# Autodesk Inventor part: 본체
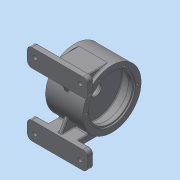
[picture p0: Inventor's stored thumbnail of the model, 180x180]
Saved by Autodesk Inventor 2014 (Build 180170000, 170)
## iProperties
Created: 2025-12
Part Number: 본체
Material: 일반
Document SubType Name: Modeling
Designer: dg
Density: 1 g/cm^3
Appearance: 기본값
Author: dg
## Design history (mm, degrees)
sketch "스케치1"
  geometry: L1 (-62, 0)-(62, 0); L2 (-62, 78)-(-57, 78); L3 (-57, 78)-(-57, 73); L4 (-57, 73)-(-40, 73); L5 (-40, 73)-(-40, 87); L6 (-40, 87)-(-8, 87); L7 (-8, 87)-(-8, 0); L8 (-8, 0)-(8, 0); L9 (8, 0)-(8, 87); L10 (8, 87)-(40, 87); L11 (40, 87)-(40, 73); L12 (40, 73)-(57, 73); L13 (57, 73)-(57, 78); L14 (57, 78)-(62, 78); L15 (62, 78)-(62, 97); L16 (62, 97)-(-62, 97); L17 (-62, 97)-(-62, 78); 2 further points
  constraints: 34 end point, 11 parallel, 4 perpendicular, 3 collinear, 3 horizontal alignment, 2 coincident, 2 point on line, 2 vertical alignment, 1 horizontal, 1 midpoint
  dimensions: "d0" = 124 distance of L1.start L1.end; "d1" = 146 diameter of L4 L1; "d2" = 156 diameter of L2 L1; "d3" = 174 diameter of L6 L1; "d4" = 194 diameter of L16 L1; "d5" = 5 distance of L2.start L2.end; "d7" = 32 distance of L5.end L6.end; "d48" = 22 distance between parallel lines of L5 L17
revolve "회전1" sketch "스케치1" stored, may be unused: angle "d8" = 90 deg
sketch "스케치2"
  geometry: L1 (0, -97)-(-100, -97); L2 (-100, -97)-(-100, -75); L3 (-100, -75)-(-61.514, -75); A1 r 97 centre (0, 0) between (0, -97) and (-61.514, -75) reference; 1 further point
  constraints: 6 end point, 2 point on circle, 1 horizontal, 1 parallel, 1 perpendicular, 1 tangent
  dimensions: "d9" = 22 distance of L1.end L2.end; "d10" = 100 distance from line of L2 L1.start
extrude "돌출1" join sketch "스케치2" stored distance "d11" = 100; taper "d12" = 0 deg
sketch "스케치3"
  geometry: L1 (-50, 22)-(150, 22); L2 (150, 22)-(150, -38); L3 (150, -38)-(-50, -38); L4 (-50, -38)-(-50, 22); 3 further points
  constraints: 8 end point, 2 parallel, 1 horizontal, 1 horizontal alignment, 1 midpoint, 1 perpendicular, 1 vertical alignment
  dimensions: "d13" = 200 distance of L2.end L3.end; "d14" = 60 distance of L3.end L1.start
extrude "돌출2" join sketch "스케치3" distance "d15" = 20; taper "d16" = 0 deg
sketch "스케치4"
  geometry: L1 (-100, -75)-(-61.514, -75) reference; L2 (-100, -75)-(-120, -75) reference; L3 (-112, -75)-(-89.83, -36.6); A1 r 97 centre (0, 0) between (-61.514, -75) and (-89.83, -36.6) reference; 1 further point
  constraints: 2 end point, 1 point on circle, 1 point on line
  dimensions: "d17" = 60 deg angle of L1 L3; "d18" = 8 distance of L2.end L3.start
extrude "돌출3" join sketch "스케치4" stored distance "d19" = 12; taper "d20" = 0 deg
fillet "모깎기1" dims "d21" = 15
sketch "스케치5"
  geometry: 3 further points
  constraints: 1 horizontal alignment
  dimensions: "d22" = 150 distance of point (125, 13) point (-25, 13); "d23" = 75 horizontal distance of point (50, -97) point (-25, 13); "d24" = 110 vertical distance of point (50, -97) point (125, 13)
hole "구멍1" sketch "스케치5" at (-25, 13), (125, 13) diameter "d25" = 13.5; stored, may be unused: countersink angle "d29" = 90 deg, drill point angle "d31" = 118 deg; dims "d26" = 6, "d27" = 33, "d28" = 2, "d30" = 8
fillet "모깎기2" dims "d32" = 3
fillet "모깎기3" dims "d33" = 3
fillet "모깎기4" dims "d34" = 3
fillet "모깎기5" dims "d35" = 3
fillet "모깎기6" dims "d36" = 3
fillet "모깎기7" dims "d37" = 3
fillet "모깎기8" dims "d38" = 3
fillet "모깎기9" dims "d39" = 3
fillet "모깎기10" dims "d40" = 3
fillet "모깎기11" dims "d41" = 3
fillet "모깎기12" dims "d42" = 3
fillet "모깎기13" dims "d43" = 3
sketch "스케치6"
  geometry: L1 (23.383, -39)-(37.148, -62.842); L2 (-23.383, -39)-(-37.148, -62.842); L3 (0, -25.5)-(0, -73); A1 r 73 centre (0, 0) between (37.148, -62.842) and (-37.148, -62.842) reference; A2 r 27 centre (0, -52.5) between (23.383, -39) and (-23.383, -39); 1 further point
  constraints: 6 end point, 6 point on circle, 2 tangent, 2 vertical alignment, 1 centre point, 1 midpoint, 1 vertical
  dimensions: "d44" = 54 diameter of A2; "d45" = 52.5 distance of A1.centre A2.centre; "d46" = 30 deg angle of L1 L3; "d47" = 30 deg angle of L3 L2
extrude "돌출4" join sketch "스케치6" distance "d49" = 17; taper "d50" = 0 deg
sketch "스케치7"
  geometry: A1 r 27 centre (0, -52.5) between (23.383, -39) and (-23.383, -39) reference; 1 further point
  constraints: 1 coincident
hole "구멍2" sketch "스케치7" at (0, -52.5) diameter "d51" = 42; stored, may be unused: countersink angle "d55" = 90 deg, drill point angle "d57" = 0 deg; dims "d52" = 6, "d53" = 33, "d54" = 2, "d56" = 3.05
hole "구멍3" diameter "d60" = 42; stored, may be unused: countersink angle "d64" = 90 deg, drill point angle "d66" = 0 deg; dims "d61" = 6, "d62" = 44.5, "d63" = 1.95, "d65" = 12, "d103" = 10, "d104" = 10
sketch "스케치9"
  geometry: C1 r 78 at (0, 0) reference; 1 further point
  constraints: 1 vertical alignment
  dimensions: "d67" = 85 distance of C1.centre point (0, 85)
hole "구멍4" sketch "스케치9" at (0, 85) diameter "d68" = 6.647; stored, may be unused: countersink angle "d72" = 90 deg, drill point angle "d74" = 118 deg; dims "d69" = 16, "d70" = 44.5, "d71" = 1.95, "d73" = 18
chamfer "모따기1" distance "d78" = 1; stored, may be unused: second distance "d79" = 2, angle "d80" = 45 deg
chamfer "모따기2" distance "d81" = 1; stored, may be unused: second distance "d82" = 2, angle "d83" = 45 deg
sketch "스케치10"
  geometry: C1 r 87 at (0, 0) reference; 2 further points
  constraints: 1 coincident, 1 vertical alignment
  dimensions: "d84" = 52.5 distance of point (0, -52.5) point (0, 0)
hole "구멍5" sketch "스케치10" at (0, 0), (0, -52.5) diameter "d85" = 38; stored, may be unused: countersink angle "d89" = 90 deg, drill point angle "d91" = 118 deg; dims "d86" = 16, "d87" = 42, "d88" = 12, "d90" = 18
chamfer "모따기3" distance "d92" = 1; stored, may be unused: second distance "d93" = 2, angle "d94" = 45 deg
fillet "모깎기14" dims "d95" = 0.6
fillet "모깎기15" dims "d96" = 3
fillet "모깎기16" dims "d97" = 3
fillet "모깎기17" dims "d98" = 3
fillet "모깎기18" dims "d99" = 3
node "작업 평면1"
sketch "스케치11"
  geometry: L1 (-53, 75.66)-(-53, 91.18) reference; L2 (-9, 69.84)-(-47, 69.84) reference; L3 (-9, 41.914)-(-9, 69.84) reference; L4 (3, 35.269)-(-3, 35.269) reference; L5 (9, 69.84)-(9, 41.914) reference; L6 (47, 69.84)-(9, 69.84) reference; L7 (53, 91.18)-(53, 75.66) reference; L8 (47, 97)-(-47, 97) reference; L9 (53, -75.66)-(53, -91.18) reference; L10 (9, -69.84)-(47, -69.84) reference; L11 (9, -41.914)-(9, -69.84) reference; L12 (-3, -35.269)-(3, -35.269) reference; L13 (-9, -69.84)-(-9, -41.914) reference; L14 (-47, -69.84)-(-9, -69.84) reference; L15 (-53, -91.18)-(-53, -75.66) reference; L16 (47, -97)-(-47, -97) reference; L17 (62, 97)-(62, -97) reference; L18 (-62, 97)-(-62, -97) reference; 3 further points
  constraints: 1 coincident, 1 horizontal alignment, 1 midpoint, 13 other
feature "엠보싱1" sketch "스케치11" dims "d101" = 0.5, "d102" = 0
node "솔리드1"
mirror "대칭1"
pattern_circular "원형 패턴1" dims angle "d76" = 360 deg
mirror "대칭2"
node "투영된 루프1"
other parameters: "d100" = 97
